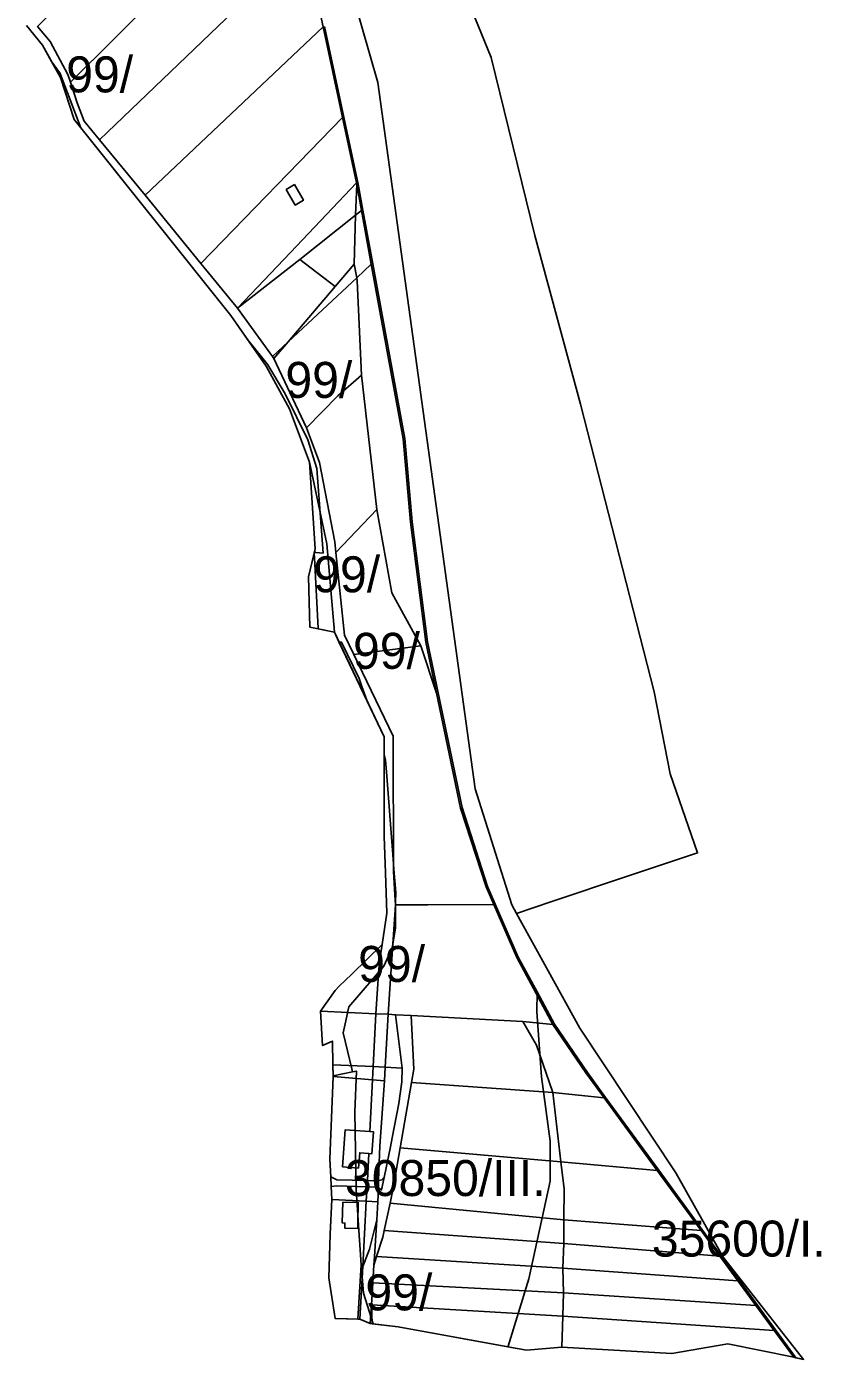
# Model space of a CAD drawing. Extents: x -535894 to -532827, y -1165802 to -1163635.
# Drawn here: x -533158 to -532827, y -1165802 to -1165247 of the extents above; entities that cross this region are included whole.
import ezdxf

# ---------------------------------------------------------------- set-up
doc = ezdxf.new("R2010")
doc.units = 0
for name, color, linetype in [('BPEJ_s', 7, 'Continuous'), ('ostatni_s', 7, 'Continuous'), ('trav_porost_s', 7, 'Continuous'), ('voda_s', 7, 'Continuous')]:
    doc.layers.add(name, color=color, linetype=linetype)

msp = doc.modelspace()

# ---------------------------------------------------------------- linework, layer by layer
at = {"layer": 'BPEJ_s'}
for points in [[(-532973.81, -1165236.01), (-532964.21, -1165259.48), (-532945.97, -1165333.71), (-532926.98, -1165404.07), (-532896.21, -1165523.88), (-532889.53, -1165558.14), (-532878.16, -1165591.08), (-532908.13, -1165601.07), (-532938.91, -1165611.34), (-532953.65, -1165616.26), (-532927.21, -1165664.12), (-532887.26, -1165724.36), (-532867.49, -1165759.55), (-532833.91, -1165802.16), (-532837.133, -1165801.503), (-532837.38, -1165801.168), (-532845.607, -1165789.921), (-532853.204, -1165779.528), (-532860.724, -1165769.255), (-532868.243, -1165758.971), (-532876.041, -1165748.305), (-532894.362, -1165723.248), (-532916.475, -1165693.021), (-532924.108, -1165682.584), (-532937.819, -1165662.486), (-532945.064, -1165649.039), (-532952.897, -1165634.501), (-532962.481, -1165612.478), (-532965.694, -1165605.088), (-532976.364, -1165572.211), (-532986.352, -1165524.318), (-532990.773, -1165503.102), (-532997.177, -1165453.032), (-533000.256, -1165418.383), (-533013.57, -1165345.583), (-533017.667, -1165323.165), (-533019.657, -1165312.29), (-533019.776, -1165311.643), (-533025.608, -1165284.384), (-533033.684, -1165246.624)], [(-532945.064, -1165649.039), (-532945.227, -1165657.244), (-532943.26, -1165684.34), (-532939.6, -1165711.26), (-532939.6, -1165727.83), (-532948.52, -1165768.6), (-532957.152, -1165796.648), (-532957.254, -1165796.905), (-533003, -1165788.63), (-533013.447, -1165787.382), (-533017.43, -1165774.62), (-533018.42, -1165762.8), (-533019.64, -1165744.17), (-533020.47, -1165731.41), (-533021.03, -1165699.01), (-533020.38, -1165682.03), (-533022.04, -1165682.32), (-533022.332, -1165681.09), (-533025.91, -1165666.02), (-533025.04, -1165662.36), (-533023.51, -1165655.23), (-533021.85, -1165653.29), (-533009.03, -1165638.23), (-533005.45, -1165630.68), (-533004.13, -1165622.47), (-533004.03, -1165611.58), (-533003.99, -1165607.59), (-533004.73, -1165597.84), (-533005.2, -1165591.78), (-533007.83, -1165557.29), (-533008.203, -1165552.363), (-533008.21, -1165552.27), (-533008.846, -1165550.096), (-533008.86, -1165542.74), (-533015.911, -1165527.873), (-533018.108, -1165521.731), (-533019.3, -1165518.4), (-533026.6, -1165503.27), (-533026.892, -1165503.208), (-533027.687, -1165503.04), (-533029.56, -1165499.09), (-533036.321, -1165497.69), (-533036.337, -1165497.392), (-533037.905, -1165468.116), (-533038.011, -1165466.134), (-533037.926, -1165465.79), (-533037.344, -1165465.843), (-533034.26, -1165466.13), (-533036.87, -1165430.9), (-533040.6, -1165418.9), (-533050.15, -1165399.71), (-533057.38, -1165387.57), (-533059.418, -1165385.017), (-533065.753, -1165377.081), (-533072.82, -1165367.05), (-533135.282, -1165288.862), (-533135.978, -1165287.047), (-533142.009, -1165271.315), (-533143.831, -1165266.563), (-533143.97, -1165266.2), (-533144.257, -1165265.797), (-533147.519, -1165261.21), (-533151.29, -1165254.43), (-533157.9, -1165246.26)], [(-533033.684, -1165246.624), (-533025.608, -1165284.384), (-533019.776, -1165311.643), (-533019.657, -1165312.29), (-533017.667, -1165323.165), (-533013.57, -1165345.583), (-533000.256, -1165418.383), (-532997.177, -1165453.032), (-532990.773, -1165503.102), (-532986.352, -1165524.318), (-532976.364, -1165572.211), (-532965.694, -1165605.088), (-532962.481, -1165612.478), (-532952.897, -1165634.501), (-532945.064, -1165649.039)]]:
    msp.add_lwpolyline(points, dxfattribs=at)
for points in [[(-533135.978, -1165287.047), (-533135.282, -1165288.862), (-533138.08, -1165285.36), (-533143.81, -1165267.88), (-533147.519, -1165261.21), (-533144.257, -1165265.797), (-533143.97, -1165266.2), (-533143.831, -1165266.563), (-533142.009, -1165271.315)], [(-533036.87, -1165430.9), (-533034.26, -1165466.13), (-533037.344, -1165465.843), (-533037.926, -1165465.79), (-533037.58, -1165464.39), (-533039.93, -1165428.22), (-533048.28, -1165406.03), (-533057.97, -1165388.13), (-533065.753, -1165377.081), (-533059.418, -1165385.017), (-533057.38, -1165387.57), (-533050.15, -1165399.71), (-533040.6, -1165418.9)], [(-533036.337, -1165497.392), (-533036.321, -1165497.69), (-533039.75, -1165496.98), (-533040.44, -1165475.96), (-533038.011, -1165466.134), (-533037.905, -1165468.116)], [(-533018.108, -1165521.731), (-533015.911, -1165527.873), (-533027.687, -1165503.04), (-533026.892, -1165503.208), (-533026.6, -1165503.27), (-533019.3, -1165518.4)], [(-533025.91, -1165666.02), (-533022.332, -1165681.09), (-533022.04, -1165682.32), (-533030.055, -1165684.016), (-533030.17, -1165679.38), (-533030.42, -1165669.49), (-533034.47, -1165671.41), (-533035.33, -1165657.07), (-533029.26, -1165648.36), (-533027.52, -1165646.64), (-533022.33, -1165641.59), (-533009.63, -1165629.23), (-533007.66, -1165616.19), (-533008.26, -1165599.32), (-533008.78, -1165584.18), (-533008.846, -1165550.096), (-533008.21, -1165552.27), (-533008.203, -1165552.363), (-533007.83, -1165557.29), (-533005.2, -1165591.78), (-533004.73, -1165597.84), (-533003.99, -1165607.59), (-533004.03, -1165611.58), (-533004.13, -1165622.47), (-533005.45, -1165630.68), (-533009.03, -1165638.23), (-533021.85, -1165653.29), (-533023.51, -1165655.23), (-533025.04, -1165662.36)], [(-532837.133, -1165801.503), (-532838.03, -1165801.32), (-532865.54, -1165795.7), (-532888.93, -1165799.76), (-532934.73, -1165797.08), (-532949.49, -1165798.31), (-532957.254, -1165796.905), (-532957.152, -1165796.648), (-532948.52, -1165768.6), (-532939.6, -1165727.83), (-532939.6, -1165711.26), (-532943.26, -1165684.34), (-532945.227, -1165657.244), (-532945.064, -1165649.039), (-532937.819, -1165662.486), (-532924.108, -1165682.584), (-532916.475, -1165693.021), (-532894.362, -1165723.248), (-532876.041, -1165748.305), (-532868.243, -1165758.971), (-532860.724, -1165769.255), (-532853.204, -1165779.528), (-532845.607, -1165789.921), (-532837.38, -1165801.168)], [(-533018.42, -1165762.8), (-533019.857, -1165785.354), (-533029.32, -1165785.09), (-533031.86, -1165768.21), (-533031.38, -1165750.02), (-533030.69, -1165735.48), (-533030.94, -1165730.11), (-533031.13, -1165726.05), (-533031.47, -1165718.72), (-533030.05, -1165684.22), (-533030.055, -1165684.016), (-533022.04, -1165682.32), (-533020.38, -1165682.03), (-533021.03, -1165699.01), (-533020.47, -1165731.41), (-533019.64, -1165744.17)], [(-533017.43, -1165774.62), (-533013.447, -1165787.382), (-533013.8, -1165787.34), (-533014.65, -1165787.24), (-533018.93, -1165785.38), (-533019.857, -1165785.354), (-533018.42, -1165762.8)]]:
    msp.add_lwpolyline(points, close=True, dxfattribs=at)
at = {"layer": 'ostatni_s'}
for points in [[(-533021.55, -1165234.47), (-533011.43, -1165270.01), (-532970.84, -1165564.38), (-532955.6, -1165612.74), (-532953.65, -1165616.26), (-532927.21, -1165664.12), (-532887.26, -1165724.36), (-532867.49, -1165759.55), (-532833.91, -1165802.16), (-532838.03, -1165801.32), (-532846.26, -1165790.07), (-532853.86, -1165779.68), (-532861.38, -1165769.41), (-532868.89, -1165759.12), (-532876.69, -1165748.46), (-532895.01, -1165723.4), (-532917.12, -1165693.17), (-532924.76, -1165682.74), (-532938.47, -1165662.64), (-532953.54, -1165634.66), (-532963.13, -1165612.63), (-532966.34, -1165605.24), (-532977.01, -1165572.37), (-532986.99, -1165524.47), (-532991.41, -1165503.26), (-532997.81, -1165453.19), (-533000.89, -1165418.54), (-533014.2, -1165345.74), (-533018.3, -1165323.32), (-533020.29, -1165312.45), (-533020.4, -1165311.8), (-533026.24, -1165284.54), (-533034.31, -1165246.78), (-533040.38, -1165218.35)], [(-533153.35, -1165246.57), (-533148.1, -1165252.82), (-533140.71, -1165266.61), (-533139.66, -1165269.87), (-533136.9, -1165278.38), (-533133.87, -1165286.06), (-533127.5, -1165293.84), (-533108.53, -1165316.98), (-533085.21, -1165345.43), (-533069.91, -1165364.08), (-533055.45, -1165384.16), (-533054.81, -1165385.05), (-533041.17, -1165413.85), (-533035.8, -1165428.41), (-533029.4, -1165461.46), (-533028.93, -1165465.91), (-533025.3, -1165500.3), (-533021.44, -1165508.35), (-533005.12, -1165542.35), (-533004.95, -1165598.83), (-533004.39, -1165608.49), (-533004.15, -1165612.67), (-533006.05, -1165641.45), (-533007.17, -1165658.34), (-533012.33, -1165658.17), (-533011.2, -1165641.49), (-533010.83, -1165636.13), (-533009.63, -1165629.23), (-533007.66, -1165616.19), (-533008.26, -1165599.32), (-533008.78, -1165584.18), (-533008.86, -1165542.74), (-533029.56, -1165499.09), (-533032.72, -1165462.3), (-533039.93, -1165428.22), (-533048.28, -1165406.03), (-533057.97, -1165388.13), (-533072.82, -1165367.05), (-533138.08, -1165285.36), (-533143.81, -1165267.88), (-533151.29, -1165254.43), (-533157.9, -1165246.26)]]:
    msp.add_lwpolyline(points, dxfattribs=at)
for points in [[(-533049.68, -1165314.54), (-533046.22, -1165312.53), (-533042.47, -1165319.02), (-533045.93, -1165321.02)], [(-533044.05, -1165343.66), (-533029.31, -1165355), (-533048.83, -1165378), (-533055.45, -1165384.16), (-533069.91, -1165364.08)], [(-533012.33, -1165658.17), (-533007.17, -1165658.34), (-533008.34, -1165680.37), (-533013.39, -1165680.14)], [(-533008.34, -1165680.37), (-533008.65, -1165686.03), (-533013.66, -1165685.61), (-533013.39, -1165680.14)], [(-533013.66, -1165685.61), (-533008.65, -1165686.03), (-533010.61, -1165713.22), (-533011.13, -1165727.66), (-533012.01, -1165727.69), (-533015.84, -1165727.6), (-533015.26, -1165716.37), (-533013.9, -1165716.47), (-533013.25, -1165707.37), (-533014.78, -1165707.25)], [(-533014.78, -1165707.25), (-533013.25, -1165707.37), (-533013.9, -1165716.47), (-533015.26, -1165716.37), (-533019.02, -1165716.08), (-533019.55, -1165722.45), (-533026.17, -1165721.9), (-533025.05, -1165706.48)], [(-533012.01, -1165727.69), (-533011.13, -1165727.66), (-533011.24, -1165730.7), (-533012.06, -1165730.37), (-533015.98, -1165730.26), (-533015.84, -1165727.6)], [(-533012.06, -1165730.37), (-533011.24, -1165730.7), (-533011.45, -1165736.54), (-533016.29, -1165736.27), (-533015.98, -1165730.26)], [(-533026.09, -1165736.68), (-533019.61, -1165736.78), (-533019.76, -1165745.41), (-533019.83, -1165747.61), (-533025.26, -1165747.48), (-533025.22, -1165745.34), (-533026.27, -1165745.32)], [(-533016.29, -1165736.27), (-533011.45, -1165736.54), (-533011.87, -1165744.03), (-533015, -1165756.19), (-533017.76, -1165763.5)], [(-533011.87, -1165744.03), (-533012.14, -1165748.28), (-533012.84, -1165759.3), (-533013.08, -1165762.85), (-533013.56, -1165770.31), (-533014.15, -1165779.42), (-533014.65, -1165787.24), (-533018.93, -1165785.38), (-533017.76, -1165763.5), (-533015, -1165756.19)]]:
    msp.add_lwpolyline(points, close=True, dxfattribs=at)
at = {"layer": 'trav_porost_s'}
for points in [[(-533055.7, -1165149.58), (-533052.58, -1165165.52), (-533049.49, -1165180.28), (-533139.66, -1165269.87), (-533140.71, -1165266.61), (-533148.1, -1165252.82), (-533153.35, -1165246.57)], [(-533049.49, -1165180.28), (-533041.97, -1165211.69), (-533127.5, -1165293.84), (-533133.87, -1165286.06), (-533136.9, -1165278.38), (-533139.66, -1165269.87)], [(-533041.97, -1165211.69), (-533040.38, -1165218.35), (-533034.31, -1165246.78), (-533108.53, -1165316.98), (-533127.5, -1165293.84)], [(-533026.24, -1165284.54), (-533085.21, -1165345.43), (-533108.53, -1165316.98), (-533034.31, -1165246.78)], [(-533020.4, -1165311.8), (-533047.82, -1165340.75), (-533069.91, -1165364.08), (-533085.21, -1165345.43), (-533026.24, -1165284.54)], [(-533020.29, -1165312.45), (-533020.71, -1165325.23), (-533044.05, -1165343.66), (-533069.91, -1165364.08), (-533047.82, -1165340.75), (-533020.4, -1165311.8)], [(-533049.68, -1165314.54), (-533045.93, -1165321.02), (-533042.47, -1165319.02), (-533046.22, -1165312.53)], [(-533018.3, -1165323.32), (-533020.71, -1165325.23), (-533020.29, -1165312.45)], [(-533018.3, -1165323.32), (-533014.2, -1165345.74), (-533020.29, -1165351.41), (-533021.4, -1165345.66), (-533020.71, -1165325.23)], [(-533020.71, -1165325.23), (-533021.4, -1165345.66), (-533029.31, -1165355), (-533044.05, -1165343.66)], [(-533020.29, -1165351.41), (-533048.83, -1165378), (-533029.31, -1165355), (-533021.4, -1165345.66)], [(-533020.29, -1165351.41), (-533014.2, -1165345.74), (-533000.89, -1165418.54), (-532997.81, -1165453.19), (-532991.41, -1165503.26), (-532986.99, -1165524.47), (-532993.56, -1165504.76), (-533005.56, -1165482.73), (-533011.83, -1165447.98), (-533018.33, -1165391.89), (-533020.07, -1165352.56)], [(-533020.07, -1165352.56), (-533018.33, -1165391.89), (-533028.16, -1165400.59), (-533041.17, -1165413.85), (-533054.81, -1165385.05), (-533048.83, -1165378), (-533020.29, -1165351.41)], [(-533055.45, -1165384.16), (-533048.83, -1165378), (-533054.81, -1165385.05)], [(-533018.33, -1165391.89), (-533011.83, -1165447.98), (-533028.93, -1165465.91), (-533029.4, -1165461.46), (-533035.8, -1165428.41), (-533041.17, -1165413.85), (-533028.16, -1165400.59)], [(-533032.72, -1165462.3), (-533029.56, -1165499.09), (-533039.75, -1165496.98), (-533040.44, -1165475.96), (-533037.58, -1165464.39), (-533039.93, -1165428.22)], [(-533011.83, -1165447.98), (-533005.56, -1165482.73), (-532993.56, -1165504.76), (-533021.44, -1165508.35), (-533025.3, -1165500.3), (-533028.93, -1165465.91)], [(-532993.56, -1165504.76), (-532986.99, -1165524.47), (-532977.01, -1165572.37), (-532966.34, -1165605.24), (-532963.13, -1165612.63), (-532990.62, -1165612.65), (-533004.15, -1165612.67), (-533004.39, -1165608.49), (-533004.95, -1165598.83), (-533005.12, -1165542.35), (-533021.44, -1165508.35)], [(-532990.62, -1165612.65), (-532963.13, -1165612.63), (-532953.54, -1165634.66), (-532938.47, -1165662.64), (-532951, -1165661.3), (-532997.56, -1165658.85), (-533004.03, -1165658.51), (-533005.63, -1165658.42), (-533007.17, -1165658.34), (-533006.05, -1165641.45), (-533004.15, -1165612.67)], [(-533009.63, -1165629.23), (-533010.83, -1165636.13), (-533011.2, -1165641.49), (-533012.33, -1165658.17), (-533035.33, -1165657.07), (-533029.26, -1165648.36), (-533027.52, -1165646.64), (-533022.33, -1165641.59)], [(-533035.33, -1165657.07), (-533012.33, -1165658.17), (-533013.39, -1165680.14), (-533030.17, -1165679.38), (-533030.42, -1165669.49), (-533034.47, -1165671.41)], [(-532997.56, -1165658.85), (-532996.45, -1165681.15), (-532997.44, -1165686.82), (-533002.12, -1165713.97), (-533005.03, -1165730.85), (-533006.36, -1165737.02), (-533008.83, -1165748.52), (-533009.41, -1165751.23), (-533011.98, -1165759.36), (-533013.08, -1165762.85), (-533012.84, -1165759.3), (-533012.14, -1165748.28), (-533011.87, -1165744.03), (-533011.45, -1165736.54), (-533011.24, -1165730.7), (-533009.87, -1165731.53), (-533008.79, -1165726.42), (-533006.19, -1165713.61), (-533005.43, -1165709.83), (-533002.65, -1165695.46), (-533001.54, -1165687.53), (-533001.5, -1165686.54), (-533001.3, -1165680.76), (-533004.03, -1165658.51)], [(-533005.63, -1165658.42), (-533004.03, -1165658.51), (-533001.3, -1165680.76), (-533008.34, -1165680.37), (-533007.17, -1165658.34)], [(-532951, -1165661.3), (-532945.26, -1165671.22), (-532938.52, -1165690.97), (-532997.44, -1165686.82), (-532996.45, -1165681.15), (-532997.56, -1165658.85)], [(-532951, -1165661.3), (-532938.47, -1165662.64), (-532924.76, -1165682.74), (-532917.12, -1165693.17), (-532938.52, -1165690.97), (-532945.26, -1165671.22)], [(-533013.39, -1165680.14), (-533013.66, -1165685.61), (-533030.05, -1165684.22), (-533030.17, -1165679.38)], [(-533030.05, -1165684.22), (-533013.66, -1165685.61), (-533014.78, -1165707.25), (-533025.05, -1165706.48), (-533026.17, -1165721.9), (-533019.55, -1165722.45), (-533019.02, -1165716.08), (-533015.26, -1165716.37), (-533015.84, -1165727.6), (-533028.54, -1165727.28), (-533031.13, -1165726.05), (-533031.47, -1165718.72)], [(-533001.3, -1165680.76), (-533001.5, -1165686.54), (-533001.54, -1165687.53), (-533002.65, -1165695.46), (-533005.43, -1165709.83), (-533006.19, -1165713.61), (-533008.79, -1165726.42), (-533009.72, -1165727.34), (-533011.13, -1165727.66), (-533010.61, -1165713.22), (-533008.65, -1165686.03), (-533008.34, -1165680.37)], [(-532997.44, -1165686.82), (-532938.52, -1165690.97), (-532935.09, -1165719.88), (-533002.12, -1165713.97)], [(-532938.52, -1165690.97), (-532917.12, -1165693.17), (-532895.01, -1165723.4), (-532935.09, -1165719.88)], [(-533002.12, -1165713.97), (-532935.09, -1165719.88), (-532933.75, -1165731.04), (-532933.84, -1165743.96), (-533006.36, -1165737.02), (-533005.03, -1165730.85)], [(-532935.09, -1165719.88), (-532895.01, -1165723.4), (-532876.69, -1165748.46), (-532933.84, -1165743.96), (-532933.75, -1165731.04)], [(-533031.13, -1165726.05), (-533028.54, -1165727.28), (-533015.84, -1165727.6), (-533015.98, -1165730.26), (-533028.61, -1165729.89), (-533030.94, -1165730.11)], [(-533008.79, -1165726.42), (-533009.87, -1165731.53), (-533011.24, -1165730.7), (-533011.13, -1165727.66), (-533009.72, -1165727.34)], [(-533028.61, -1165729.89), (-533015.98, -1165730.26), (-533016.29, -1165736.27), (-533030.69, -1165735.48), (-533030.94, -1165730.11)], [(-533030.69, -1165735.48), (-533016.29, -1165736.27), (-533017.76, -1165763.5), (-533018.93, -1165785.38), (-533029.32, -1165785.09), (-533031.86, -1165768.21), (-533031.38, -1165750.02)], [(-533026.09, -1165736.68), (-533026.27, -1165745.32), (-533025.22, -1165745.34), (-533025.26, -1165747.48), (-533019.83, -1165747.61), (-533019.76, -1165745.41), (-533019.61, -1165736.78)], [(-533006.36, -1165737.02), (-532933.84, -1165743.96), (-532933.91, -1165753.88), (-533008.83, -1165748.52)], [(-532933.84, -1165743.96), (-532876.69, -1165748.46), (-532868.89, -1165759.12), (-532933.91, -1165753.88)], [(-533008.83, -1165748.52), (-532933.91, -1165753.88), (-532934.37, -1165764.2), (-533011.98, -1165759.36), (-533009.41, -1165751.23)], [(-532933.91, -1165753.88), (-532868.89, -1165759.12), (-532861.38, -1165769.41), (-532934.37, -1165764.2)], [(-533011.98, -1165759.36), (-532934.37, -1165764.2), (-532934.06, -1165774.43), (-533013.56, -1165770.31), (-533013.08, -1165762.85)], [(-532934.37, -1165764.2), (-532861.38, -1165769.41), (-532853.86, -1165779.68), (-532934.06, -1165774.43)], [(-533013.56, -1165770.31), (-532934.06, -1165774.43), (-532934.35, -1165784.1), (-533014.15, -1165779.42)], [(-533014.15, -1165779.42), (-533013.8, -1165787.34), (-533014.65, -1165787.24)], [(-533014.15, -1165779.42), (-532934.35, -1165784.1), (-532934.73, -1165797.08), (-532949.49, -1165798.31), (-533003, -1165788.63), (-533013.8, -1165787.34)], [(-532934.06, -1165774.43), (-532853.86, -1165779.68), (-532846.26, -1165790.07), (-532934.35, -1165784.1)], [(-532934.35, -1165784.1), (-532846.26, -1165790.07), (-532838.03, -1165801.32), (-532865.54, -1165795.7), (-532888.93, -1165799.76), (-532934.73, -1165797.08)]]:
    msp.add_lwpolyline(points, close=True, dxfattribs=at)
at = {"layer": 'voda_s'}
msp.add_lwpolyline([(-532973.81, -1165236.01), (-532964.21, -1165259.48), (-532945.97, -1165333.71), (-532926.98, -1165404.07), (-532896.21, -1165523.88), (-532889.53, -1165558.14), (-532878.16, -1165591.08), (-532908.13, -1165601.07), (-532938.91, -1165611.34), (-532953.65, -1165616.26), (-532955.6, -1165612.74), (-532970.84, -1165564.38), (-533011.43, -1165270.01), (-533021.55, -1165234.47)], dxfattribs=at)

# ---------------------------------------------------------------- texts
at = {"layer": 'BPEJ_s'}
for s, p in [('99/', (-533141.401, -1165274.066)), ('99/', (-533050.007, -1165401.419)), ('99/', (-533038.381, -1165482.446)), ('99/', (-533021.799, -1165514.339)), ('99/', (-533019.66, -1165644.854)), ('30850/III.', (-533025.14, -1165734.091)), ('35600/I.', (-532897.194, -1165759.327)), ('99/', (-533016.652, -1165781.741))]:
    msp.add_text(s, height=15, dxfattribs=at).set_placement(p)

doc.saveas('drawing.dxf')
